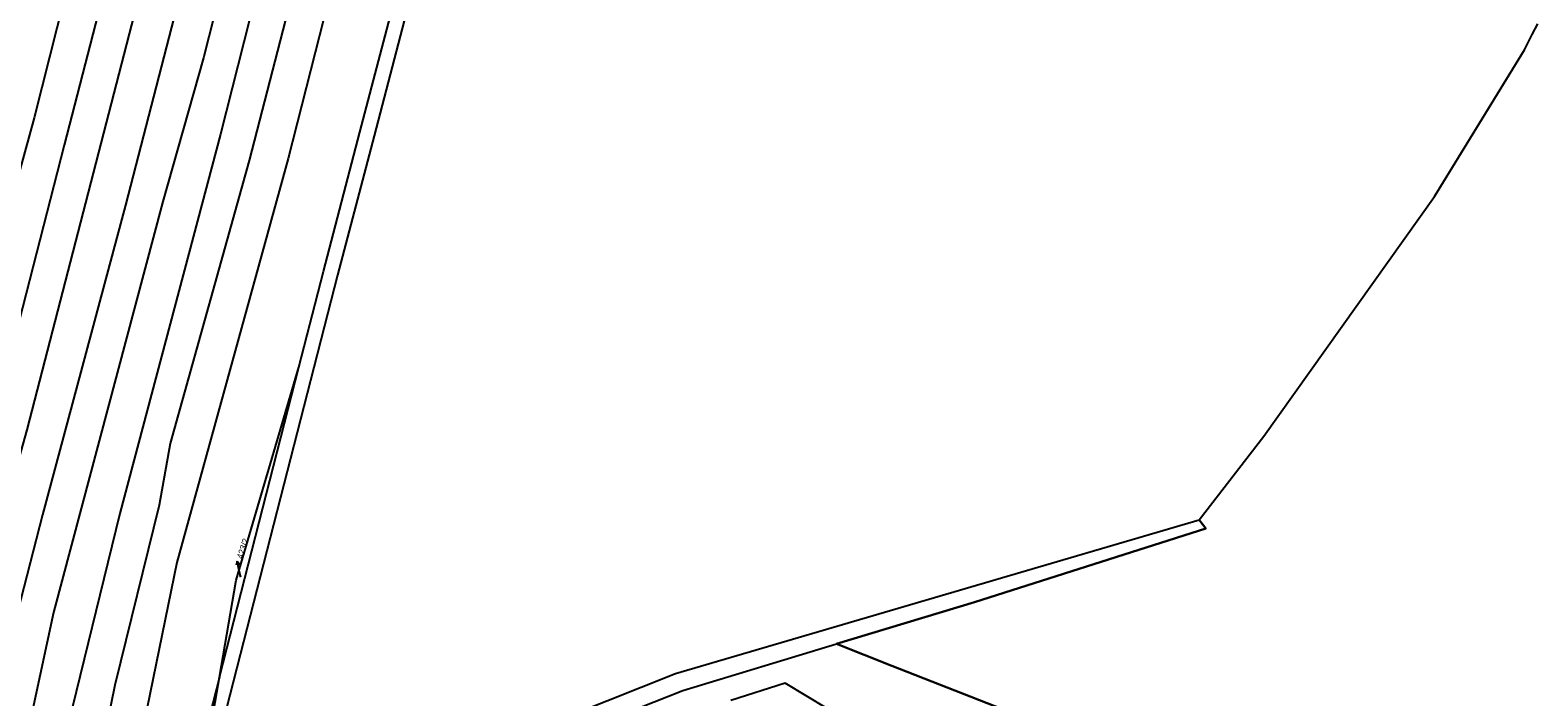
# Model space of a CAD drawing. Extents: x -757266 to -753360, y -1162585 to -1157740.
# Drawn here: x -753899.7 to -753487.7, y -1161203.3 to -1161021 of the extents above; entities that cross this region are included whole.
import ezdxf

# ---------------------------------------------------------------- set-up
doc = ezdxf.new("R2010")
doc.units = 0
for name, color, linetype in [('Hranice kat_území', 7, 'Continuous'), ('Hranice parcel', 7, 'Continuous'), ('Parcelní čísla', 7, 'Continuous'), ('Pop  PČ popisy', 7, 'Continuous')]:
    doc.layers.add(name, color=color, linetype=linetype)

msp = doc.modelspace()

# ---------------------------------------------------------------- linework, layer by layer
at = {"layer": 'Hranice kat_území'}
msp.add_lwpolyline([(-753585.43, -1161592.54), (-753610.05, -1161559.66), (-753622.52, -1161542.76), (-753648.71, -1161507.25), (-753651.25, -1161503.81), (-753649.77, -1161489.62), (-753645.01, -1161470.99), (-753634.18, -1161423.7), (-753610.1, -1161343.95), (-753604.08, -1161318.63), (-753598.56, -1161283.7), (-753581.49, -1161231.01), (-753585.4, -1161229.08), (-753618.86, -1161212.57), (-753664.17, -1161194.77), (-753679.35, -1161188.8), (-753641.6, -1161177.34), (-753578.41, -1161157.2), (-753580.23, -1161154.82), (-753562.51, -1161131.98), (-753515.94, -1161066.49), (-753491.34, -1161026.31), (-753489.2, -1161022.19), (-753487.66, -1161019.22)], dxfattribs=at)
at = {"layer": 'Hranice parcel'}
for p, q in [((-753491.34, -1161026.31), (-753489.2, -1161022.19)), ((-753489.2, -1161022.19), (-753487.66, -1161019.22)), ((-753847.92, -1161197.83), (-753826.22, -1161113.11)), ((-753723.33, -1161196.91), (-753580.23, -1161154.82)), ((-753580.23, -1161154.82), (-753578.41, -1161157.2)), ((-753679.35, -1161188.8), (-753664.17, -1161194.77))]:
    msp.add_line(p, q, dxfattribs=at)
for points in [[(-753782.33, -1160641.82), (-753791.1, -1160664.88), (-753809.92, -1160745.87), (-753825.27, -1160804), (-753833.19, -1160829.43), (-753849.7, -1160892.19), (-753862.41, -1160939.81), (-753865.38, -1160955.67), (-753890.34, -1161052.44), (-753915.1, -1161148.52), (-753926.99, -1161189.35), (-753943.49, -1161257.41)], [(-753799.92, -1160655.58), (-753813.51, -1160718.31), (-753832.63, -1160794.46), (-753857.91, -1160881.66), (-753871.61, -1160938.15), (-753898.61, -1161044.97), (-753925.23, -1161141.94), (-753937.34, -1161184.25), (-753951.11, -1161242.82), (-753956.28, -1161260.81)], [(-753773.83, -1160653.45), (-753783.64, -1160684.26), (-753798.71, -1160740.75), (-753824.26, -1160833.57), (-753827.25, -1160847.57), (-753851.82, -1160936.08), (-753856.41, -1160957.22), (-753861.16, -1160974.43), (-753862.8, -1160983.12), (-753869.19, -1161008.46), (-753900.58, -1161130.26), (-753915.16, -1161182.19), (-753930.46, -1161254.08)], [(-753767.62, -1160665.12), (-753783.88, -1160718.7), (-753805.92, -1160803.85), (-753820.21, -1160860.45), (-753833.38, -1160908.18), (-753852.62, -1160987.63), (-753873.63, -1161068.78), (-753896.28, -1161153.46), (-753906.51, -1161193.2), (-753918.95, -1161250.61)], [(-753760.2, -1160676.93), (-753763.36, -1160689.01), (-753769.15, -1160705.38), (-753790.87, -1160787.46), (-753829.23, -1160932.91), (-753840.46, -1160981.76), (-753852.3, -1161028.54), (-753863.37, -1161067.84), (-753893.25, -1161180.16), (-753907.87, -1161248.01)], [(-753751.53, -1160686.65), (-753761.52, -1160717.14), (-753776.71, -1160767.63), (-753785.14, -1160803.91), (-753792.35, -1160831.22), (-753809.69, -1160896.78), (-753817.51, -1160926.03), (-753820.58, -1160942.58), (-753847.62, -1161049.45), (-753875.17, -1161153.16), (-753890.36, -1161215.25), (-753895.56, -1161243.71)], [(-753743.71, -1160693.8), (-753753.4, -1160723.43), (-753768.69, -1160777.91), (-753783.02, -1160830.03), (-753784.83, -1160839.44), (-753796.68, -1160881.02), (-753818.67, -1160974.67), (-753839.78, -1161056.59), (-753861.4, -1161133.97), (-753864.39, -1161150.81), (-753876.53, -1161200.05), (-753884.85, -1161240.81)], [(-753734.79, -1160701.95), (-753752, -1160752.71), (-753762.45, -1160792.65), (-753767.84, -1160812.44), (-753784.69, -1160879.85), (-753807.09, -1160969.37), (-753829.14, -1161056.07), (-753859.63, -1161166.55), (-753874.28, -1161238.21)], [(-753718.69, -1160716.69), (-753725.37, -1160746.24), (-753742.27, -1160809.64), (-753763.26, -1160884.69), (-753769.39, -1160906.26), (-753781.18, -1160955.34), (-753794.18, -1161005.77), (-753805.66, -1161049.9), (-753815.66, -1161088), (-753848.71, -1161217.04), (-753853.07, -1161232.85), (-753769.73, -1161215.34), (-753723.33, -1161196.91)], [(-753826.22, -1161113.11), (-753819.53, -1161086.99), (-753809.54, -1161048.89), (-753798.05, -1161004.77), (-753785.07, -1160954.41), (-753773.22, -1160905.17), (-753767.11, -1160883.61), (-753746.12, -1160808.56), (-753729.24, -1160745.21), (-753718.69, -1160716.69)], [(-753580.23, -1161154.82), (-753562.51, -1161131.98), (-753515.94, -1161066.49), (-753491.34, -1161026.31)], [(-753847.92, -1161197.83), (-753843.35, -1161171.34), (-753826.22, -1161113.11)], [(-753578.41, -1161157.2), (-753641.6, -1161177.34), (-753679.35, -1161188.8)], [(-753894.35, -1161247.6), (-753892.04, -1161246.81), (-753854.68, -1161237.3), (-753768.78, -1161220.31), (-753721.32, -1161201.55), (-753679.35, -1161188.8)], [(-753664.17, -1161194.77), (-753618.86, -1161212.57), (-753585.4, -1161229.08)], [(-753874.48, -1161239.19), (-753855.94, -1161235.51), (-753849.47, -1161206.79), (-753847.92, -1161197.83)], [(-753847.92, -1161197.83), (-753852.59, -1161216.05), (-753857.21, -1161234.01), (-753874.28, -1161238.21)], [(-753681.85, -1161206.42), (-753693.35, -1161199.49), (-753708.21, -1161204.25)]]:
    msp.add_lwpolyline(points, dxfattribs=at)
at = {"layer": 'Pop  PČ popisy'}
for p, q in [((-753843.054, -1161166.185), (-753843.336, -1161167.268)), ((-753842.43, -1161169.12), (-753843.054, -1161166.185)), ((-753843.054, -1161166.185), (-753842.356, -1161167.06)), ((-753842.13, -1161170.56), (-753842.43, -1161169.12))]:
    msp.add_line(p, q, dxfattribs=at)

# ---------------------------------------------------------------- texts
at = {"layer": 'Parcelní čísla'}
msp.add_text('423/2', height=1.7, rotation=72, dxfattribs=at).set_placement((-753841.641, -1161165.672))

doc.saveas('drawing.dxf')
